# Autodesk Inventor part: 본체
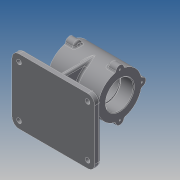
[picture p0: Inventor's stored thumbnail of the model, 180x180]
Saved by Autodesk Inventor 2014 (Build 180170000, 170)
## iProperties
Created: 2015-12
Part Number: 본체
Material: Generic
Document SubType Name: Modeling
Designer: test_23
Density: 1 g/cm^3
Appearance: Default
Author: test_23
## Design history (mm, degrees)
sketch "스케치1"
  geometry: L1 (-42.5, 0)-(42.5, 0); L2 (42.5, 23.5)-(42.5, 37); L3 (42.5, 37)-(-42.5, 37); L4 (-42.5, 37)-(-42.5, 23.5); L5 (0, 0)-(0, 37); L6 (-42.5, 23.5)-(-20.5, 23.5); L7 (-20.5, 23.5)-(-20.5, 21); L8 (-20.5, 21)-(20.5, 21); L9 (20.5, 21)-(20.5, 23.5); L10 (20.5, 23.5)-(42.5, 23.5); 1 further point
  constraints: 20 end point, 5 perpendicular, 4 parallel, 2 midpoint, 2 vertical alignment, 1 coincident, 1 horizontal
  dimensions: "d0" = 85 distance between parallel lines of L2 L4; "d1" = 37 distance of L3.end L1.start; "d2" = 22 distance of L4.end L6.end; "d3" = 22 distance of L2.start L9.end; "d4" = 23.5 distance between parallel lines of L1 L6; "d5" = 23.5 distance between parallel lines of L1 L10; "d6" = 21 distance between parallel lines of L1 L8
revolve "회전1" sketch "스케치1" stored, may be unused: angle "d7" = 90 deg
node "작업 평면1"
sketch "스케치2"
  geometry: L1 (-80, 55)-(60, 55); L2 (60, 55)-(60, -55); L3 (60, -55)-(-80, -55); L4 (-80, -55)-(-80, 55); L5 (0, 0)-(31.454, 0)
  constraints: 10 end point, 2 parallel, 2 perpendicular, 1 horizontal, 1 other
  dimensions: "d9" = 140 distance of L1.start L1.end; "d10" = 110 distance of L3.end L1.start; "d11" = 80 distance from line of L4 L5.start
extrude "돌출1" join sketch "스케치2" distance "d12" = 10; taper "d13" = 0 deg
sketch "스케치3"
  geometry: L1 (-42.5, -37)-(42.5, -37) reference; L2 (-60, -70)-(80, -70) reference; L3 (-20.948, -37)-(-25, -70); L4 (20.948, -37)-(25, -70); L5 (0, -37)-(0, -70); 1 further point
  constraints: 6 end point, 5 point on line, 1 midpoint, 1 perpendicular
  dimensions: "d14" = 97 deg angle of L2 L3; "d15" = 97 deg angle of L2 L4; "d16" = 25 distance of L5.end L3.end; "d17" = 50 distance of L4.end L3.end
sketch "스케치4"
  geometry: L1 (-25, 6)-(25, 6); L2 (25, 6)-(25, -6); L3 (25, -6)-(-25, -6); L4 (-25, -6)-(-25, 6); L5 (0, 0)-(0, 3.303); L6 (0, 0)-(-5.412, 0)
  constraints: 12 end point, 3 parallel, 2 perpendicular, 1 horizontal, 2 other
  dimensions: "d18" = 12 distance of L3.end L1.start; "d19" = 50 distance of L1.start L1.end
extrude "돌출2" join sketch "스케치4" stored distance "d20" = 10; taper "d21" = 0 deg
feature "면 기울기1" dims angle "d22" = 7 deg
feature "면 기울기2" dims angle "d23" = 7 deg
sketch "스케치5"
  geometry: L1 (-70, 55)-(-70, -55) reference; L2 (0, 37)-(-70, 37); L3 (0, -37)-(-70, -37); A1 r 37 centre (0, 0) between (0, 37) and (0, -37) reference; 1 further point
  constraints: 4 end point, 2 perpendicular, 2 point on circle, 2 point on line, 2 tangent
sketch "스케치6"
  geometry: L1 (-4, 37)-(4, 37); L2 (4, 37)-(4, -37); L3 (4, -37)-(-4, -37); L4 (-4, -37)-(-4, 37); L5 (0, 0)-(54.074, 0); L6 (0, 0)-(0, -19.474)
  constraints: 12 end point, 3 perpendicular, 2 parallel, 1 horizontal, 2 other
  dimensions: "d24" = 8 distance of L1.start L1.end; "d25" = 74 distance of L3.end L1.start
extrude "돌출3" join sketch "스케치6" stored distance "d26" = 10; taper "d27" = 0 deg
sketch "스케치7"
  geometry: C1 r 7 at (0, 37); C2 r 7 at (-37, 0); C3 r 7 at (0, -37); C4 r 7 at (37, 0); 1 further point
  constraints: 4 centre point, 2 vertical alignment, 10 other
  dimensions: "d28" = 14 diameter of C1; "d31" = 360 deg dimension on point (0, 0) C1.centre (derived)
sketch "스케치8"
  geometry: L1 (-42.5, 37)-(42.5, 37) reference; L2 (-42.5, -37)-(-42.5, 37) reference; L3 (-42.5, 37)-(-42.5, 44); L4 (-42.5, 44)-(-30.048, 44); L5 (-30.048, 44)-(-27.5, 37); 1 further point
  constraints: 6 end point, 1 collinear, 1 perpendicular, 1 point on line
  dimensions: "d33" = 110 deg angle of L1 L5; "d34" = 15 distance from line of L3 L5.end; "d35" = 7 distance between parallel lines of L1 L4
extrude "돌출4" join sketch "스케치7" distance "d36" = 15; taper "d37" = 0 deg
extrude "돌출5" join sketch "스케치7" distance "d38" = 15; taper "d39" = 0 deg
fillet "모깎기1" dims "d40" = 12
sketch "스케치10"
  geometry: C1 r 4 at (-48, 43); C2 r 4 at (68, 43); C3 r 4 at (68, -43); C4 r 4 at (-48, -43); A1 r 12 centre (68, 43) between (80, 43) and (68, 55) reference; A2 r 12 centre (-48, 43) between (-48, 55) and (-60, 43) reference; A3 r 12 centre (-48, -43) between (-60, -43) and (-48, -55) reference; A4 r 12 centre (68, -43) between (68, -55) and (80, -43) reference; 1 further point
  constraints: 4 centre point, 4 coincident, 3 equal radius
  dimensions: "d41" = 8 diameter of C1
extrude "돌출6" cut sketch "스케치10" distance "d42" = 15; taper "d43" = 0 deg
fillet "모깎기2" dims "d44" = 0.3
chamfer "모따기1" distance "d45" = 1; stored, may be unused: second distance "d46" = 2, angle "d47" = 45 deg
fillet "모깎기3" dims "d48" = 3
fillet "모깎기4" dims "d49" = 3
fillet "모깎기5" dims "d50" = 3
sketch "스케치11"
  geometry: A1 r 7 centre (0, 0) between (0.662, 6.969) and (0.662, -6.969) reference; A2 r 7 centre (37, -37) between (30.031, -36.338) and (43.969, -36.338) reference; A3 r 7 centre (74, 0) between (73.338, -6.969) and (73.338, 6.969) reference; A4 r 7 centre (37, 37) between (43.969, 36.338) and (30.031, 36.338) reference; 4 further points
  constraints: 4 coincident
hole "구멍1" sketch "스케치11" at (37, 37), (74, 0), (37, -37), (0, 0) diameter "d51" = 2.487; stored, may be unused: countersink angle "d55" = 90 deg, drill point angle "d57" = 118 deg; dims "d52" = 9, "d53" = 4, "d54" = 2, "d56" = 11
chamfer "모따기2" distance "d58" = 1; stored, may be unused: second distance "d59" = 2, angle "d60" = 45 deg
fillet "모깎기6" dims "d62" = 3
fillet "모깎기7" dims "d63" = 3
sketch "스케치14"
  geometry: L1 (0, 0)-(26.163, -26.163); A1 r 37 centre (0, 0) between (9.104, -35.863) and (35.863, -9.104) reference; 1 further point
  constraints: 2 end point, 1 point on circle
sketch "스케치15"
  geometry: C1 r 21 at (0, 0) reference; C2 r 21 at (0, 0)
  constraints: 1 centre point, 1 coincident, 1 concentric
extrude "돌출7" cut sketch "스케치15" stored distance "d64" = 15; taper "d65" = 0 deg
node "작업 평면8"
sketch "스케치16"
  geometry: 2 further points
  constraints: 1 coincident, 1 other
feature "엠보싱1" sketch "스케치16" dims "d12" = 10, "d66" = 0.5, "d67" = 0
node "솔리드1"
mirror "대칭1"
mirror "대칭2"
